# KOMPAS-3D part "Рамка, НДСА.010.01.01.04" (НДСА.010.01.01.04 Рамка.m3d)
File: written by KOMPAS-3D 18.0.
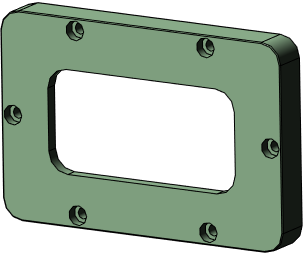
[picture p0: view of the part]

Document properties: Автор: Саня; Организация: Санек; Полное имя файла: F:\Temp\НДСА.010.01.01.04 Рамка.m3d

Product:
- Part/product: Рамка  | designation НДСА.010.01.01.04
    Материал: АМг6 ГОСТ 4784-97 (density 2640 kg/m3)
    Масса: 0.293096
    additional columns: <item xmlns="http://appius.ru/pdm" xmlns:xs="http://www.w3.org/2001/XMLSchema" x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; <item xmlns="http://appius.ru/pdm" xmlns:xs="http://www.w3.org/2001/XMLSchema" x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; <item xmlns="http://appius.ru/pdm" xmlns:xs="http://www.w3.org/2001/XMLSchema" x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; <item xmlns="http://appius.ru/pdm" xmlns:xs="http://www.w3.org/2001/XMLSchema" x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; <item xmlns="http://appius.ru/pdm" xmlns:xs="http://www.w3.org/2001/XMLSchema" x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; <item xmlns="http://appius.ru/pdm" xmlns:xs="http://www.w3.org/2001/XMLSchema" x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; <item xmlns="http://appius.ru/pdm" xmlns:xs="http://www.w3.org/2001/XMLSchema" x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

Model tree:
1. Эскиз:1
2. Операция выдавливания:1
     Расстояние 1 = 18
3. Скругление:1  (with: Операция выдавливания:1)
     Радиус = 10
4. Эскиз:2  (with: Операция выдавливания:1)
5. Вырезать элемент выдавливания:1
     Расстояние 1 = 12
6. Скругление:2  (with: Вырезать элемент выдавливания:1)
     Радиус = 9.5
7. Скругление:3  (with: Вырезать элемент выдавливания:1, Скругление:2)
     Радиус = 0.5
8. Фаска:1  (with: Операция выдавливания:1, Скругление:1)
     Угол = 45; Длина 1 = 0.5; Длина 2 = 0.5
9. Эскиз:3  (with: Операция выдавливания:1)
10. Вырезать элемент выдавливания:2
     Расстояние 1 = 30
11. Эскиз:4  (with: Операция выдавливания:1, Вырезать элемент выдавливания:2)
12. Вырезать элемент выдавливания:3  (labels: АМг6 ГОСТ 4784-97; SYSTEM_PROPERTY_ADDITIONAL_FOR:9.000000)
     Расстояние 1 = 5

Expressions: v87/2; v89/2; v91/2; v125/2; v127/2
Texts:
  НДСА.010.01.01.04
